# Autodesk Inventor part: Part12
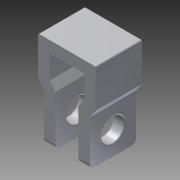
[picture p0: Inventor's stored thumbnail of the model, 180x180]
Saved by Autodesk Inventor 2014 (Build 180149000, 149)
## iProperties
Created: 2009-11
Part Number: Part12
Document SubType Name: Modeling
Designer: pokornp
Density: 1 g/cm^3
Material: Generic
Appearance: Default
Author: pokornp
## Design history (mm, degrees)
sketch "Sketch3"
  geometry: L1 (-75, 0)-(0, 0); L2 (0, 0)-(0, 50); L3 (0, 50)-(-125, 50); L4 (-125, 50)-(-125, -116.281); L5 (-125, -116.281)-(-100, -150.599); L6 (-100, -150.599)-(-100, -350); L7 (-100, -350)-(-50, -350); L8 (-50, -350)-(-50, -134.319); L9 (-50, -134.319)-(-75, -100); L10 (-75, -100)-(-75, 0); L11 (50, -350)-(50, -134.319); L12 (100, -350)-(50, -350); L13 (100, -150.599)-(100, -350); L14 (125, -116.281)-(100, -150.599); L15 (50, -134.319)-(75, -100); L16 (75, -100)-(75, 0); L17 (125, 50)-(125, -116.281); L18 (0, 50)-(125, 50); L19 (75, 0)-(0, 0); 1 further point
  constraints: 38 end point, 8 symmetric about line, 7 parallel, 1 coincident, 1 horizontal, 1 perpendicular
  dimensions: "t" = 50 distance between parallel lines of L3 L1; "d1" = 50 distance between parallel lines of L4 L10 (= t); "d2" = 50 distance between parallel lines of L5 L9 (= t); "d3" = 50 distance between parallel lines of L8 L6 (= t); "d4" = 75 distance between parallel lines of L2 L10; "d5" = 50 distance between parallel lines of L8 L2; "d8" = 100 distance of L16.end L15.end; "d9" = 400 distance between parallel lines of L12 L18
extrude "Extrusion1" new body sketch "Sketch3" distance "d6" = 200; taper "d7" = 0 deg
hole "Hole1" diameter "d12" = 100; stored, may be unused: countersink angle "d16" = 90 deg, drill point angle "d18" = 118 deg; dims "d10" = 100, "d11" = 100, "d13" = 6, "d14" = 4, "d15" = 2, "d17" = 8
fillet "Fillet1" dims "d19" = 20
fillet "Fillet2" dims "d20" = 5
fillet "Fillet3" dims "d21" = 5
body "Solid1"
